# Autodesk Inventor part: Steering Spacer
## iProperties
Shininess: 77.0
Angle Display Precision: 2
Document Length Units: 11269
Document Angle Units: 11279
Document Time Units: 11290
Document Mass Units: 11283
Document Length Units Precision: 3
Document Angle Units Precision: 2
Compacted: True
Created: 2001-08
Part Number: Steering Spacer
Document SubType Name: Modeling
Designer: Martin Budgell
Density: 0.0
Volumn: 0.0
Area: 0.0
PropertySet Name: Model Information
Control State: 0
Master: False
Checked Out: False
Author: Martin Budgell
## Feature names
1. Extrusion1
2. Chamfer1
